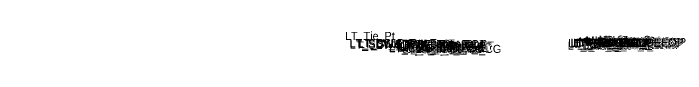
# Model space of a CAD drawing. Extents: x -26 to 4229, y -10 to 9523.
# Drawn here: x 3000 to 3166.4, y 1498.9 to 1504.9 of the extents above; entities that cross this region are included whole.
import ezdxf

# ---------------------------------------------------------------- set-up
doc = ezdxf.new("R2010")
doc.units = 0
doc.layers.add('Default', color=7, linetype='Continuous')

msp = doc.modelspace()

# ---------------------------------------------------------------- texts
at = {"layer": 'Default'}
for s, height, p in [('LT_Tie_Pt', 2, (3082.1, 1502.79)), ('LT_SDWK_Out_Top', 2, (3083.24, 1500.99)), ('LT_CSLP_Pnt', 2, (3085.17, 1501.02)), ('LT_PV2_OEEOP', 2, (3137.37, 1501)), ('LT_PV1_OEEOP', 2, (3137.94, 1501.12)), ('LT_PV2_IEEOP', 2, (3138.02, 1501)), ('LT_PV1_IEEOP', 2, (3138.58, 1501.12)), ('LT_PV2_PGL1', 2, (3138.95, 1501)), ('LT_PV2_PGL', 2, (3139.28, 1501)), ('LT_PV1_PGL', 2, (3139.84, 1501.25)), ('MI_Face In', 2, (3139.96, 1501.41)), ('MI_Bot In', 2, (3140.95, 1501.25)), ('MI_Top In', 2, (3141.67, 1501.66)), ('RT_PV2_OEEOP', 2, (3144.91, 1501.15)), ('MI_Crown', 2, (3144.93, 1501.87)), ('RT_PV1_OEEOP', 2, (3145.47, 1501.27)), ('RT_PV2_IEEOP', 2, (3145.55, 1501.15)), ('MI_Face Out', 2, (3145.9, 1501.56)), ('MI_Top Out', 2, (3146.11, 1501.81)), ('RT_PV1_IEEOP', 2, (3146.12, 1501.27)), ('RT_PV2_PGL1', 2, (3146.48, 1501.15)), ('RT_PV2_PGL', 2, (3146.81, 1501.15)), ('MI_Bot Out', 2, (3146.91, 1501.4)), ('RT_PV1_PGL', 2, (3147.38, 1501.4)), ('LT_SDWK_Out_Bot', 2, (3083.27, 1500.66)), ('LT_Sub_Trench_Out_DLT', 2, (3085.49, 1500.82)), ('LT_SDWK_In_Top', 2, (3089.86, 1500.89)), ('LT_SDWK_In_Bot', 2, (3089.89, 1500.56)), ('LT_CG1_Shelf_Out', 2, (3093.05, 1499.75)), ('LT_CG_Top_Face', 2, (3094.76, 1500.78)), ('LT_CG_Top_BOC', 2, (3095.28, 1500.78)), ('LT_CG_Bot_BOC', 2, (3095.31, 1499.76)), ('LT_CG_Top_Gut', 2, (3095.74, 1500.28)), ('LT_Sub_OEOP', 2, (3096.35, 1499.5)), ('LT_Sub_OEOT_CG', 2, (3096.87, 1499.57)), ('LT_CG_Bot_IE', 2, (3099.41, 1499.82)), ('LT_Sub_OEOT', 2, (3099.58, 1499.52)), ('LT_PV2_OEOT', 2, (3099.67, 1500.15)), ('LT_PV3_OEOT', 2, (3099.67, 1499.9)), ('LT_PV1_OEOT', 2, (3100.24, 1500.4)), ('LT_Sub_OEEOP', 2, (3137.28, 1500.37)), ('LT_PV3_OEEOP', 2, (3137.37, 1500.75)), ('LT_PV3_PGL1', 2, (3138.95, 1500.75)), ('LT_PV4_PGL', 2, (3139.28, 1500.37)), ('RT_Sub_OEEOP', 2, (3144.81, 1500.52)), ('RT_PV3_OEEOP', 2, (3144.91, 1500.9)), ('RT_PV3_PGL1', 2, (3146.48, 1500.9)), ('RT_PV4_PGL', 2, (3146.81, 1500.52)), ('-', 0.0001, (3000, 1500)), ('-', 0.0001, (3000, 1500)), ('-', 0.0001, (3000, 1500)), ('-', 0.0001, (3000, 1500)), ('-', 0.0001, (3000, 1500)), ('-', 0.0001, (3000, 1500)), ('-', 0.0001, (3000, 1500))]:
    msp.add_text(s, height=height, dxfattribs=at).set_placement(p)

doc.saveas('drawing.dxf')
